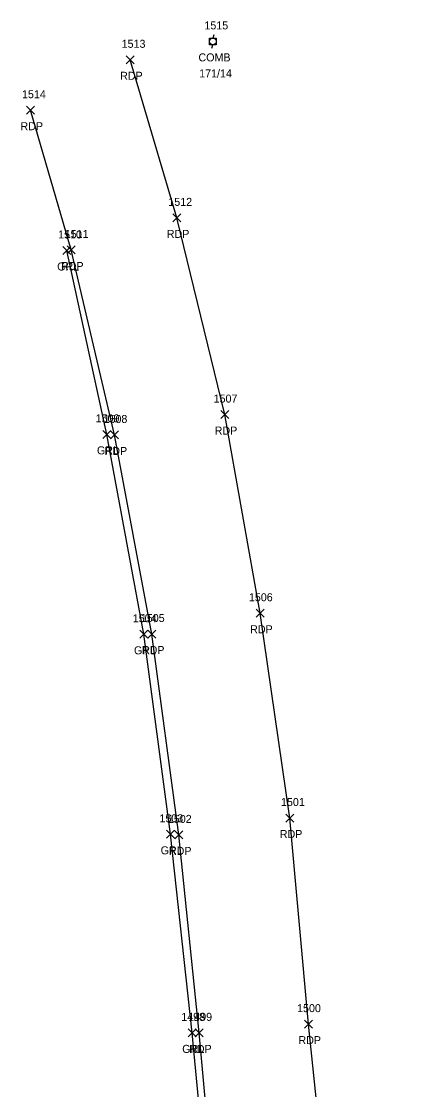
# Model space of a CAD drawing. Extents: x 1503463 to 1505240, y 712171 to 717196.
# Drawn here: x 1503463.3 to 1503558.1, y 716929.1 to 717196.1 of the extents above; entities that cross this region are included whole.
import ezdxf

# ---------------------------------------------------------------- set-up
doc = ezdxf.new("R2010")
doc.units = 0
for name, color, linetype in [('P_A', 7, 'Continuous'), ('P_I', 7, 'Continuous'), ('P_TIC', 7, 'Continuous'), ('PET', 7, 'Continuous'), ('R_A', 7, 'Continuous'), ('R_I', 7, 'Continuous'), ('R_TIC', 7, 'Continuous'), ('RGR', 7, 'Continuous'), ('U_A', 7, 'Continuous'), ('U_C', 7, 'Continuous'), ('U_I', 7, 'Continuous'), ('UP', 7, 'Continuous')]:
    doc.layers.add(name, color=color, linetype=linetype)

msp = doc.modelspace()

# ---------------------------------------------------------------- linework, layer by layer
at = {"layer": 'P_TIC'}
for points in [[(1503489.5, 717185.45), (1503491.5, 717187.45)], [(1503491.5, 717185.45), (1503489.5, 717187.45)], [(1503464.59, 717172.85), (1503466.59, 717174.85)], [(1503466.59, 717172.85), (1503464.59, 717174.85)], [(1503501.16, 717145.94), (1503503.16, 717147.94)], [(1503503.16, 717145.94), (1503501.16, 717147.94)], [(1503474.71, 717137.92), (1503476.71, 717139.92)], [(1503476.71, 717137.92), (1503474.71, 717139.92)], [(1503513.13, 717096.79), (1503515.13, 717098.79)], [(1503515.13, 717096.79), (1503513.13, 717098.79)], [(1503485.61, 717091.69), (1503487.61, 717093.69)], [(1503487.61, 717091.69), (1503485.61, 717093.69)], [(1503522.01, 717047.13), (1503524.01, 717049.13)], [(1503524.01, 717047.13), (1503522.01, 717049.13)], [(1503494.94, 717041.95), (1503496.94, 717043.95)], [(1503496.94, 717041.95), (1503494.94, 717043.95)], [(1503529.42, 716995.96), (1503531.42, 716997.96)], [(1503531.42, 716995.96), (1503529.42, 716997.96)], [(1503501.69, 716991.74), (1503503.69, 716993.74)], [(1503503.69, 716991.74), (1503501.69, 716993.74)], [(1503534.09, 716944.45), (1503536.09, 716946.45)], [(1503536.09, 716944.45), (1503534.09, 716946.45)], [(1503506.73, 716942.28), (1503508.73, 716944.28)], [(1503508.73, 716942.28), (1503506.73, 716944.28)]]:
    msp.add_lwpolyline(points, dxfattribs=at)
at = {"layer": 'PET'}
for points in [[(1503558.12, 716659.95), (1503553.68, 716721.47), (1503549.59, 716782.3), (1503545.06, 716839.19), (1503540.5, 716893.37), (1503535.09, 716945.45), (1503530.42, 716996.96), (1503523.01, 717048.13), (1503514.13, 717097.79), (1503502.16, 717146.94), (1503490.5, 717186.45)], [(1503530.11, 716659.58), (1503525.62, 716720.04), (1503521.69, 716779.87), (1503517.39, 716836.47), (1503512.47, 716891.47), (1503507.73, 716943.28), (1503502.69, 716992.74), (1503495.94, 717042.95), (1503486.61, 717092.69), (1503475.71, 717138.92), (1503465.59, 717173.85)]]:
    msp.add_lwpolyline(points, dxfattribs=at)
at = {"layer": 'R_TIC'}
for points in [[(1503473.7, 717137.79), (1503475.7, 717139.79)], [(1503475.7, 717137.79), (1503473.7, 717139.79)], [(1503483.64, 717091.84), (1503485.64, 717093.84)], [(1503485.64, 717091.84), (1503483.64, 717093.84)], [(1503492.91, 717041.87), (1503494.91, 717043.87)], [(1503494.91, 717041.87), (1503492.91, 717043.87)], [(1503499.58, 716991.89), (1503501.58, 716993.89)], [(1503501.58, 716991.89), (1503499.58, 716993.89)], [(1503504.97, 716942.27), (1503506.97, 716944.27)], [(1503506.97, 716942.27), (1503504.97, 716944.27)]]:
    msp.add_lwpolyline(points, dxfattribs=at)
at = {"layer": 'RGR'}
msp.add_lwpolyline([(1503527.84, 716659.98), (1503523.83, 716719.82), (1503519.62, 716780.55), (1503515.33, 716836.18), (1503510.92, 716891.8), (1503505.97, 716943.27), (1503500.58, 716992.89), (1503493.91, 717042.87), (1503484.64, 717092.84), (1503474.7, 717138.79)], dxfattribs=at)
at = {"layer": 'UP'}
for p, q in [((1503510.35, 717190.22), (1503510.35, 717191.88)), ((1503510.35, 717191.88), (1503512.02, 717191.88)), ((1503511.44, 717192.72), (1503511.19, 717191.88)), ((1503511.19, 717191.05), (1503511.19, 717191.05)), ((1503512.02, 717191.88), (1503512.02, 717190.22)), ((1503512.02, 717190.22), (1503510.35, 717190.22)), ((1503510.94, 717189.38), (1503511.19, 717190.22))]:
    msp.add_line(p, q, dxfattribs=at)
msp.add_circle((1503511.19, 717191.05), 0.833, dxfattribs=at)

# ---------------------------------------------------------------- texts
at = {"layer": 'P_A'}
for p in [(1503487.99, 717181.45), (1503463.07, 717168.85), (1503499.65, 717141.94), (1503473.2, 717133.92), (1503511.62, 717092.79), (1503484.1, 717087.69), (1503520.49, 717043.13), (1503493.43, 717037.95), (1503527.91, 716991.96), (1503500.18, 716987.74), (1503532.57, 716940.45), (1503505.22, 716938.28)]:
    msp.add_text('RDP', height=2, dxfattribs=at).set_placement(p)
at = {"layer": 'P_I'}
for s, p in [('1513', (1503488.37, 717189.45)), ('1514', (1503463.46, 717176.85)), ('1512', (1503500.04, 717149.94)), ('1511', (1503474.15, 717141.92)), ('1507', (1503511.36, 717100.79)), ('1508', (1503483.84, 717095.69)), ('1506', (1503520.18, 717051.13)), ('1505', (1503493.17, 717045.95)), ('1501', (1503528.21, 716999.96)), ('1502', (1503499.92, 716995.74)), ('1500', (1503532.23, 716948.45)), ('1499', (1503505.03, 716946.28))]:
    msp.add_text(s, height=2, dxfattribs=at).set_placement(p)
at = {"layer": 'R_A'}
for p in [(1503472.24, 717133.79), (1503482.19, 717087.84), (1503491.45, 717037.87), (1503498.12, 716987.89), (1503503.51, 716938.27)]:
    msp.add_text('GRL', height=2, dxfattribs=at).set_placement(p)
at = {"layer": 'R_I'}
for s, p in [('1510', (1503472.49, 717141.79)), ('1509', (1503481.87, 717095.84)), ('1504', (1503491.14, 717045.87)), ('1503', (1503497.81, 716995.89)), ('1498', (1503503.27, 716946.27))]:
    msp.add_text(s, height=2, dxfattribs=at).set_placement(p)
at = {"layer": 'U_A'}
msp.add_text('COMB', height=2, dxfattribs=at).set_placement((1503507.57, 717186.05))
at = {"layer": 'U_C'}
msp.add_text('171/14', height=2, dxfattribs=at).set_placement((1503507.75, 717182.05))
at = {"layer": 'U_I'}
msp.add_text('1515', height=2, dxfattribs=at).set_placement((1503509.06, 717194.05))

doc.saveas('drawing.dxf')
